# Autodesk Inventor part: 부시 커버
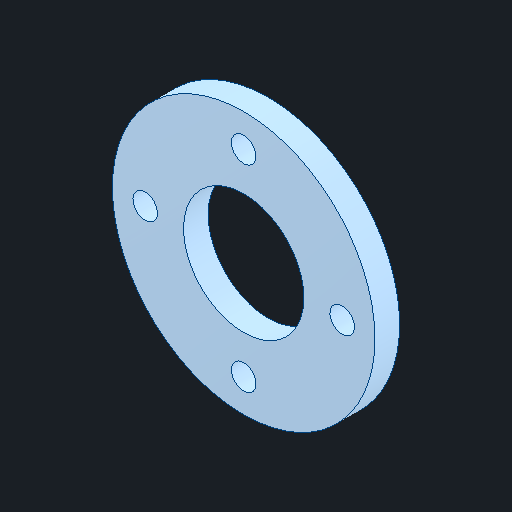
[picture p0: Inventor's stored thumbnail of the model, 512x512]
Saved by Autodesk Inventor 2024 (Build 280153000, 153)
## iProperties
Created: 2024-05
Part Number: 부시 커버
Material: 강철, 연강
Document SubType Name: Modeling
Designer: kh_501
Density: 7.85 g/cm^3
Appearance: 기본값
Sending System: Autodesk Inventor 2025
Preprocessor: ST-DEVELOPER v20
Author: jhkim
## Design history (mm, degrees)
feature "솔리드1"
node "솔리드2"
